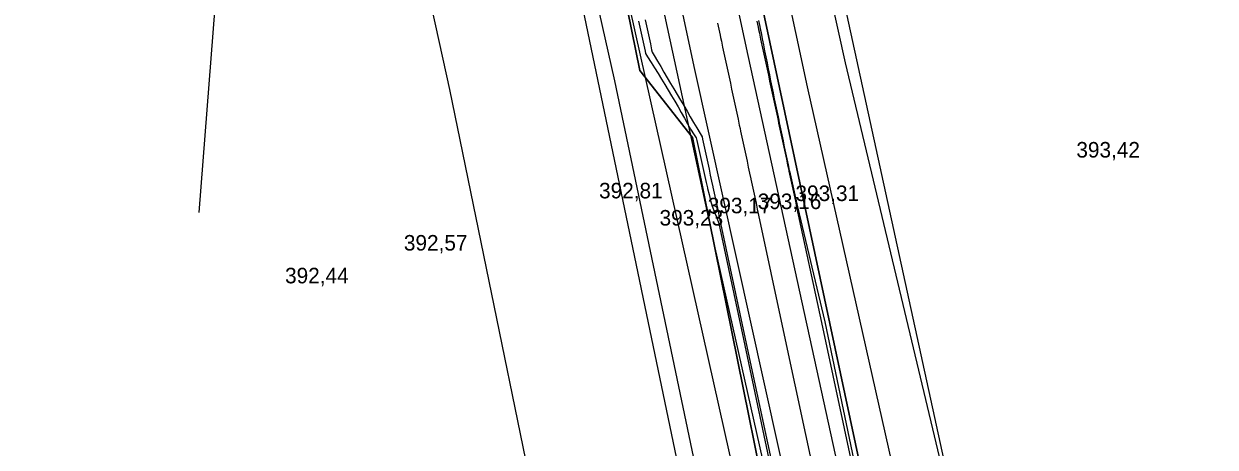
# Model space of a CAD drawing. Extents: x -574342 to -507939, y -1144044 to -1123894.
# Drawn here: x -508564.2 to -508487.6, y -1142986.9 to -1142959.6 of the extents above; entities that cross this region are included whole.
import ezdxf

# ---------------------------------------------------------------- set-up
doc = ezdxf.new("R2010")
doc.units = 0
for name, color, linetype in [('01_PARCELY_NAVRH_PC', 7, 'Continuous'), ('01_PARCELY_NAVRH_ŽP', 7, 'Continuous'), ('07_VODOVOD', 7, 'Continuous'), ('1000', 7, 'Continuous'), ('21', 7, 'Continuous'), ('37', 7, 'Continuous'), ('42', 7, 'Continuous'), ('55', 7, 'Continuous'), ('Level 255', 7, 'Continuous'), ('VRST VEDL', 7, 'Continuous')]:
    doc.layers.add(name, color=color, linetype=linetype)

msp = doc.modelspace()

# ---------------------------------------------------------------- linework, layer by layer
at = {"layer": '01_PARCELY_NAVRH_PC'}
msp.add_lwpolyline([(-508546.584, -1142847.7), (-508527.76, -1142936.34), (-508528.85, -1142941.84), (-508524.62, -1142962.65), (-508521.23, -1142966.97), (-508506.03, -1143042.25), (-508499.26, -1143041.98), (-508503.94, -1143018.7), (-508540.355, -1142847.7)], dxfattribs=at)
at = {"layer": '01_PARCELY_NAVRH_ŽP'}
for points in [[(-508551.381, -1142847.7), (-508513, -1143032.18), (-508513.37, -1143051.16), (-508506.03, -1143042.25), (-508521.23, -1142966.97), (-508524.62, -1142962.65), (-508528.85, -1142941.84), (-508527.76, -1142936.34), (-508546.584, -1142847.7)], [(-508540.355, -1142847.7), (-508503.94, -1143018.7), (-508499.26, -1143041.98), (-508491.15, -1143065.29), (-508474.05, -1143124.14), (-508467.92, -1143139.18), (-508459.97, -1143152.33), (-508456.09, -1143158.71), (-508451.57, -1143168.14), (-508437.66, -1143207.58), (-508425.52, -1143241.92), (-508422.7, -1143249.88), (-508420.04, -1143252.1), (-508417.38, -1143252.95), (-508415.56, -1143252.78), (-508448.24, -1143160.16), (-508453.75, -1143145.01), (-508465.11, -1143123.03), (-508471.48, -1143106.99), (-508484.55, -1143061.98), (-508495.62, -1143031.06), (-508523.23, -1142904.28), (-508534.61, -1142847.7)]]:
    msp.add_lwpolyline(points, dxfattribs=at)
at = {"layer": '07_VODOVOD'}
msp.add_lwpolyline([(-508640.05, -1143130.18), (-508637.48, -1143128.83), (-508626.48, -1143135.95), (-508617.09, -1143140.73), (-508602.61, -1143146.08), (-508586.87, -1143149.65), (-508578.03, -1143148.66), (-508571.02, -1143145.86), (-508562.51, -1143139.92), (-508546.01, -1143124.95), (-508535.68, -1143117.17), (-508526.75, -1143109.24), (-508521.13, -1143103.37), (-508515.47, -1143095.19), (-508511.95, -1143085.3), (-508511.14, -1143074.49), (-508510.31, -1143059.6), (-508507.36, -1143039.1), (-508508.06, -1143029.96), (-508510.42, -1143015.75), (-508519.77, -1142974.08), (-508526.08, -1142944.88), (-508540.82, -1142875.36), (-508546.434, -1142847.7)], dxfattribs=at)
at = {"layer": '1000'}
for points in [[(-508524.702, -1142959.48), (-508524.619, -1142959.866), (-508524.537, -1142960.252), (-508524.455, -1142960.639), (-508524.372, -1142961.025), (-508524.29, -1142961.412), (-508524.259, -1142961.562), (-508524.122, -1142961.78), (-508523.9, -1142962.136), (-508523.678, -1142962.493), (-508523.455, -1142962.849), (-508523.233, -1142963.206), (-508523.011, -1142963.563), (-508522.8, -1142963.921), (-508522.589, -1142964.28), (-508522.379, -1142964.64), (-508522.169, -1142964.999), (-508521.961, -1142965.358), (-508521.76, -1142965.719), (-508521.559, -1142966.08), (-508521.355, -1142966.441), (-508521.129, -1142966.797), (-508521, -1142967), (-508520.963, -1142967.165), (-508520.876, -1142967.55), (-508520.789, -1142967.936), (-508520.701, -1142968.321), (-508520.614, -1142968.707), (-508520.527, -1142969.092), (-508520.441, -1142969.478), (-508520.354, -1142969.863), (-508520.274, -1142970.22), (-508520.267, -1142970.249), (-508520.175, -1142970.633), (-508520.084, -1142971.018), (-508519.966, -1142971.397), (-508519.819, -1142971.769), (-508519.672, -1142972.142), (-508519.542, -1142972.518), (-508517.956, -1142979.95), (-508512.913, -1143003.849)], [(-508524.279, -1142959.389), (-508524.196, -1142959.775), (-508524.114, -1142960.162), (-508524.031, -1142960.548), (-508523.948, -1142960.935), (-508523.866, -1142961.321), (-508523.834, -1142961.471), (-508523.704, -1142961.69), (-508523.493, -1142962.049), (-508523.281, -1142962.408), (-508523.07, -1142962.767), (-508522.858, -1142963.126), (-508522.647, -1142963.485), (-508522.436, -1142963.844), (-508522.224, -1142964.202), (-508522.013, -1142964.561), (-508521.801, -1142964.92), (-508521.59, -1142965.279), (-508521.378, -1142965.638), (-508521.167, -1142965.997), (-508520.956, -1142966.355), (-508520.744, -1142966.714), (-508520.623, -1142966.92), (-508520.588, -1142967.085), (-508520.505, -1142967.471), (-508520.422, -1142967.858), (-508520.34, -1142968.244), (-508520.257, -1142968.63), (-508520.175, -1142969.017), (-508520.092, -1142969.403), (-508520.009, -1142969.789), (-508519.933, -1142970.147), (-508519.927, -1142970.176), (-508519.844, -1142970.562), (-508519.761, -1142970.949), (-508519.679, -1142971.335), (-508519.596, -1142971.721), (-508519.514, -1142972.108), (-508519.431, -1142972.494), (-508517.842, -1142979.926), (-508512.734, -1143003.81)], [(-508517.103, -1142959.471), (-508517.02, -1142959.857), (-508516.988, -1142960.007), (-508516.938, -1142960.243), (-508516.855, -1142960.63), (-508516.773, -1142961.016), (-508516.69, -1142961.403), (-508516.607, -1142961.789), (-508516.525, -1142962.175), (-508516.442, -1142962.562), (-508516.359, -1142962.948), (-508516.277, -1142963.334), (-508516.194, -1142963.721), (-508516.111, -1142964.107), (-508516.029, -1142964.494), (-508515.946, -1142964.88), (-508515.864, -1142965.266), (-508515.781, -1142965.653), (-508515.734, -1142965.874), (-508515.698, -1142966.039), (-508515.616, -1142966.426), (-508515.533, -1142966.812), (-508515.45, -1142967.198), (-508515.368, -1142967.585), (-508515.285, -1142967.971), (-508515.203, -1142968.357), (-508515.12, -1142968.744), (-508515.043, -1142969.101), (-508515.037, -1142969.13), (-508514.955, -1142969.517), (-508514.872, -1142969.903), (-508514.789, -1142970.289), (-508514.707, -1142970.676), (-508514.624, -1142971.062), (-508514.541, -1142971.448), (-508512.952, -1142978.88), (-508507.844, -1143002.764)], [(-508516.983, -1142959.445), (-508516.907, -1142959.833), (-508516.877, -1142959.983), (-508516.83, -1142960.22), (-508516.753, -1142960.608), (-508516.676, -1142960.996), (-508516.599, -1142961.383), (-508516.522, -1142961.771), (-508516.445, -1142962.158), (-508516.367, -1142962.546), (-508516.29, -1142962.933), (-508516.212, -1142963.321), (-508516.135, -1142963.708), (-508516.057, -1142964.096), (-508515.979, -1142964.483), (-508515.9, -1142964.87), (-508515.819, -1142965.257), (-508515.739, -1142965.644), (-508515.693, -1142965.865), (-508515.658, -1142966.031), (-508515.577, -1142966.417), (-508515.496, -1142966.804), (-508515.415, -1142967.191), (-508515.334, -1142967.577), (-508515.253, -1142967.964), (-508515.172, -1142968.351), (-508515.09, -1142968.737), (-508515.015, -1142969.095), (-508515.008, -1142969.124), (-508514.922, -1142969.51), (-508514.835, -1142969.895), (-508514.748, -1142970.281), (-508514.662, -1142970.666), (-508514.575, -1142971.052), (-508514.488, -1142971.437), (-508512.721, -1142978.831), (-508507.743, -1143002.743)]]:
    msp.add_lwpolyline(points, dxfattribs=at)
at = {"layer": '21'}
msp.add_lwpolyline([(-508519.63, -1142959.607), (-508519.548, -1142959.994), (-508519.465, -1142960.38), (-508519.433, -1142960.53), (-508519.382, -1142960.766), (-508519.3, -1142961.153), (-508519.217, -1142961.539), (-508519.135, -1142961.925), (-508519.052, -1142962.312), (-508518.969, -1142962.698), (-508518.887, -1142963.085), (-508518.804, -1142963.471), (-508518.721, -1142963.857), (-508518.639, -1142964.244), (-508518.556, -1142964.63), (-508518.474, -1142965.016), (-508518.391, -1142965.403), (-508518.308, -1142965.789), (-508518.226, -1142966.176), (-508518.178, -1142966.397), (-508518.143, -1142966.562), (-508518.06, -1142966.948), (-508517.978, -1142967.335), (-508517.895, -1142967.721), (-508517.813, -1142968.107), (-508517.73, -1142968.494), (-508517.647, -1142968.88), (-508517.565, -1142969.267), (-508517.488, -1142969.624), (-508517.482, -1142969.653), (-508517.399, -1142970.039), (-508517.317, -1142970.426), (-508517.234, -1142970.812), (-508517.151, -1142971.199), (-508517.069, -1142971.585), (-508516.986, -1142971.971), (-508515.397, -1142979.403), (-508510.289, -1143003.287)], dxfattribs=at)
at = {"layer": '37'}
for points in [[(-508511.59, -1143124.92), (-508509.54, -1143119.35), (-508506.51, -1143105.44), (-508506, -1143084.25), (-508505.31, -1143056.58), (-508505.39, -1143050.71), (-508505.49, -1143042.55), (-508509.4, -1143015.37), (-508521.08, -1142962.59), (-508532.6, -1142908.81), (-508545.204, -1142847.7)], [(-508511.59, -1143124.92), (-508509.54, -1143119.35), (-508506.51, -1143105.44), (-508506, -1143084.25), (-508505.31, -1143056.58), (-508505.39, -1143050.71), (-508505.49, -1143042.55), (-508509.4, -1143015.37), (-508521.08, -1142962.59), (-508532.6, -1142908.81), (-508545.204, -1142847.7)], [(-508541.866, -1142847.7), (-508529.22, -1142908.11), (-508517.67, -1142961.7), (-508506.14, -1143014.46), (-508500.54, -1143041.74), (-508495.34, -1143058.46)], [(-508541.866, -1142847.7), (-508529.22, -1142908.11), (-508517.67, -1142961.7), (-508506.14, -1143014.46), (-508500.54, -1143041.74), (-508495.34, -1143058.46)]]:
    msp.add_lwpolyline(points, dxfattribs=at)
at = {"layer": '42'}
for points in [[(-508560.651, -1142847.7), (-508548.46, -1142911.06), (-508536.86, -1142963.87), (-508529.29, -1143000.8), (-508523.32, -1143047.2)], [(-508560.651, -1142847.7), (-508548.46, -1142911.06), (-508536.86, -1142963.87), (-508529.29, -1143000.8), (-508523.32, -1143047.2)], [(-508510.77, -1143053.59), (-508510.65, -1143044.07), (-508514.85, -1143017.75), (-508526.24, -1142963.32), (-508538.39, -1142909.19), (-508550.685, -1142847.7)], [(-508510.77, -1143053.59), (-508510.65, -1143044.07), (-508514.85, -1143017.75), (-508526.24, -1142963.32), (-508538.39, -1142909.19), (-508550.685, -1142847.7)], [(-508445.89, -1143059.01), (-508479.63, -1143062.18), (-508484.42, -1143059.76), (-508487.39, -1143055.01), (-508499.96, -1143010.2), (-508511.4, -1142962.16), (-508523.74, -1142906.21), (-508535.517, -1142847.7)], [(-508445.89, -1143059.01), (-508479.63, -1143062.18), (-508484.42, -1143059.76), (-508487.39, -1143055.01), (-508499.96, -1143010.2), (-508511.4, -1142962.16), (-508523.74, -1142906.21), (-508535.517, -1142847.7)]]:
    msp.add_lwpolyline(points, dxfattribs=at)
at = {"layer": '55'}
for points in [[(-508548.593, -1142847.7), (-508536.61, -1142907.95), (-508524.27, -1142963.1), (-508513.79, -1143010.01), (-508509.84, -1143035.05), (-508508.31, -1143060.76)], [(-508548.593, -1142847.7), (-508536.61, -1142907.95), (-508524.27, -1142963.1), (-508513.79, -1143010.01), (-508509.84, -1143035.05), (-508508.31, -1143060.76)], [(-508492.58, -1143052.86), (-508498.99, -1143029.87), (-508513.85, -1142963.71), (-508525.48, -1142909.41), (-508538.364, -1142847.7)], [(-508492.58, -1143052.86), (-508498.99, -1143029.87), (-508513.85, -1142963.71), (-508525.48, -1142909.41), (-508538.364, -1142847.7)]]:
    msp.add_lwpolyline(points, dxfattribs=at)
at = {"layer": 'VRST VEDL'}
msp.add_lwpolyline([(-508551.951, -1142958.587), (-508552.973, -1142971.797)], dxfattribs=at)

# ---------------------------------------------------------------- texts
at = {"layer": 'Level 255'}
for s, p in [('393,42', (-508496.555, -1142968.26)), ('392,81', (-508527.245, -1142970.89)), ('393,31', (-508514.615, -1142971.06)), ('393,17', (-508520.255, -1142971.85)), ('393,16', (-508517.045, -1142971.58)), ('393,23', (-508523.355, -1142972.64)), ('392,57', (-508539.795, -1142974.25)), ('392,44', (-508547.435, -1142976.36))]:
    msp.add_text(s, height=1, dxfattribs=at).set_placement(p)

doc.saveas('drawing.dxf')
